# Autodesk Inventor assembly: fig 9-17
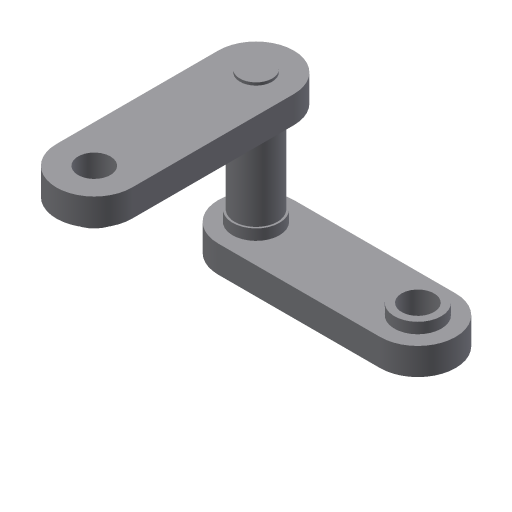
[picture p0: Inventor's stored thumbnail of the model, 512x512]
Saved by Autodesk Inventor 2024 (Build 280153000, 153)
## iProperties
Shininess: 64.0
Length Units: 11269
Angle Units: 11279
Time Units: 11290
Mass Units: 11283
Length Display Precision: 3
Angle Display Precision: 2
Created: 2002-01
Part Number: fig 9-17
Document SubType Name: Assembly
Designer: ***
Density: 0.0
Volumn: 0.0
Area: 0.0
PropertySet Name: Model Information
Control State: 0
Master: False
Checked Out: False
Author: ***
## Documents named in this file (3)
- D:\PROJECTS\Project 2023\RESOURCES INVENTOR 2024\RESOURCES INVENTOR 2024\Inventor_2023_Part\Inventor_2024_Part\c09_Inv_2024_prt\fig 9-17.iam
- D:\PROJECTS\Project 2023\RESOURCES INVENTOR 2024\RESOURCES INVENTOR 2024\Inventor_2023_Part\Inventor_2024_Part\c09_Inv_2024_prt\Part5.ipt
- D:\PROJECTS\Project 2023\RESOURCES INVENTOR 2024\RESOURCES INVENTOR 2024\Inventor_2023_Part\Inventor_2024_Part\c09_Inv_2024_prt\Part6.ipt
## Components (3 placed, 2 different names)
1. Part5:1 — Insert:1
2. Part6:1 — Insert:1, Insert:2
3. Part5:2 — Insert:2
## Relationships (2: Insert 2)
- Insert:1: Part5:1 ↔ Part6:1
- Insert:2: Part6:1 ↔ Part5:2
